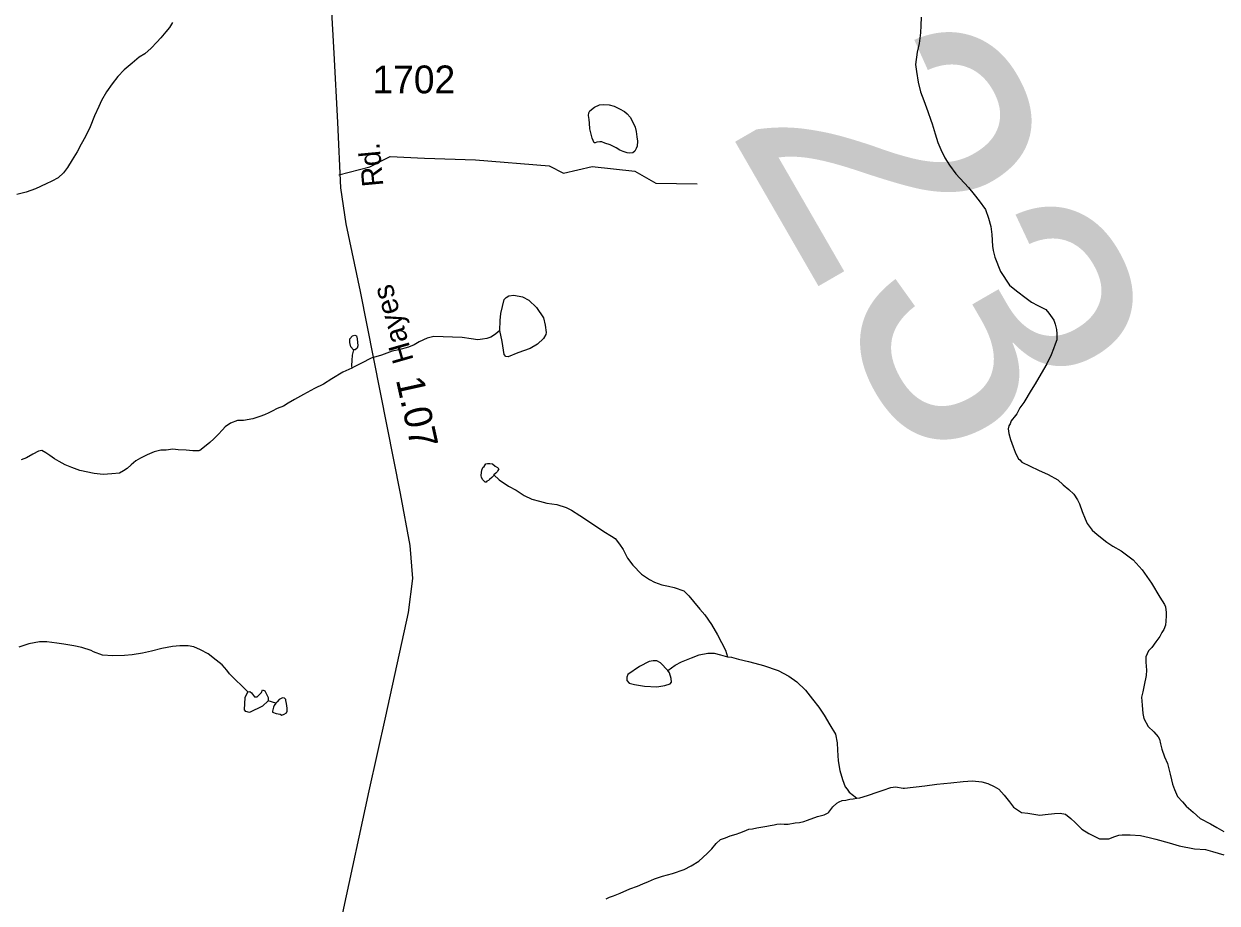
# Model space of a CAD drawing. Extents: x 2056842 to 2160602, y 826753 to 1016856.
# Drawn here: x 2104548 to 2109914, y 859964 to 863916 of the extents above; entities that cross this region are included whole.
import ezdxf

# ---------------------------------------------------------------- set-up
doc = ezdxf.new("R2010")
doc.units = 0
for name, color, linetype in [('Exist Hydrographic Creek Single Shore', 7, 'Continuous'), ('Exist Hydrographic Misc Water Feature', 7, 'Continuous'), ('Exist Road Non-System Type 51', 7, 'Continuous'), ('Exist Road Secondary Mileage Hundredths English Label', 7, 'Continuous'), ('Exist Road Secondary Structure Standard Bridge Number Label', 7, 'Continuous'), ('Exist Road Secondary Type 51 Attributed', 7, 'Continuous'), ('Exist Road Secondary Type 51 Label', 7, 'Continuous'), ('Exist Road Secondary Type 51 Number Label', 7, 'Continuous')]:
    doc.layers.add(name, color=color, linetype=linetype)

msp = doc.modelspace()

# ---------------------------------------------------------------- linework, layer by layer
at = {"layer": 'Exist Hydrographic Creek Single Shore'}
for points in [[(2108583.2, 863946), (2108581.5, 863908.1), (2108579.5, 863875.9), (2108573.7, 863828.1), (2108565.7, 863788), (2108558.2, 863733.9), (2108562.1, 863702.1), (2108570.3, 863654.2), (2108580.3, 863610.1), (2108594.9, 863572.1), (2108612.5, 863522.4), (2108626.6, 863482.5), (2108632.8, 863466.2), (2108646.7, 863422.2), (2108658.8, 863382.4), (2108670.9, 863350.5), (2108689.2, 863314.4), (2108711.1, 863280.7), (2108739.6, 863242.6), (2108795.8, 863181), (2108821.9, 863149), (2108844, 863120.9), (2108871.7, 863081), (2108886.2, 863043.1), (2108896.1, 863005.2), (2108900.2, 862969.2), (2108904.5, 862917.4), (2108906.5, 862897.2), (2108914.7, 862867.2), (2108940.6, 862803.6), (2108981, 862741.5), (2109011.1, 862715.8), (2109055, 862683.6), (2109078.8, 862665.8), (2109107.1, 862649.7), (2109129.2, 862639.9), (2109143.4, 862632.1), (2109157.1, 862616.2), (2109179.1, 862584.1), (2109185.4, 862566), (2109191.6, 862542.4), (2109193.4, 862522.3), (2109193.8, 862496.2), (2109185.8, 862476.3), (2109177.6, 862456), (2109168, 862427.9), (2109148.1, 862388), (2109122.1, 862344), (2109096.2, 862298), (2109078.4, 862269.8), (2109044.7, 862213.7), (2109026.7, 862189.7), (2109012.6, 862163.7), (2109007, 862155.7), (2108988.6, 862131.7), (2108982.8, 862117.6), (2108976.9, 862109.6), (2108974.8, 862095.7), (2108977.1, 862075.5), (2108985.3, 862047.8), (2108996.8, 862015.6), (2109005.2, 861991.6), (2109015, 861971.9), (2109021.4, 861961.6), (2109027.3, 861955.8), (2109035.3, 861945.7), (2109111.4, 861909.8), (2109153.6, 861890), (2109197.7, 861866.3), (2109221.7, 861844.5), (2109247.8, 861822.6), (2109269.9, 861802.6), (2109285.9, 861776.7), (2109295.7, 861758.5), (2109307.8, 861724.6), (2109320.1, 861690.8), (2109330, 861671), (2109352.1, 861640.8), (2109374.3, 861620.9), (2109418.4, 861587), (2109444.8, 861569.2), (2109482.3, 861547.2), (2109506.5, 861529.4), (2109536.5, 861507.5), (2109576.9, 861461.5), (2109619.1, 861401.6), (2109656.8, 861339.8), (2109677.1, 861306), (2109681.4, 861296), (2109685.1, 861269.8), (2109685.3, 861256), (2109683.5, 861232), (2109681.8, 861213.9), (2109673.8, 861194), (2109665.4, 861179.9), (2109655.8, 861162), (2109637.8, 861137.9), (2109619.7, 861113.8)], [(2106022.5, 862368.5), (2105982.3, 862350.2), (2105932.9, 862320.4), (2105894.7, 862296.1), (2105854.8, 862277.8), (2105804.9, 862249.6), (2105765.1, 862227.7), (2105737.1, 862211.6), (2105715.1, 862197.6), (2105687.6, 862187.5), (2105665.1, 862175.5), (2105649.3, 862167.3), (2105629.4, 862159.4), (2105609.3, 862151.1), (2105577.3, 862140.9), (2105535.3, 862133.1), (2105509.4, 862133), (2105477.3, 862120.8), (2105453.7, 862104.9), (2105441.6, 862090.8), (2105421.7, 862070.7), (2105401.8, 862050.6), (2105383.7, 862034.8), (2105359.6, 862014.5), (2105339.9, 861998.4), (2105334.1, 861996.4), (2105307.7, 861996.3), (2105277.7, 862000.1), (2105241.9, 862001.8), (2105218.1, 862003.8), (2105188.1, 861999.9), (2105163.7, 861999.9), (2105133.6, 861991.9), (2105101.8, 861979.7), (2105071.9, 861963.5), (2105052.2, 861951.5), (2105030, 861933.4), (2105012, 861917.4), (2104995.8, 861907.2), (2104978.6, 861897.3), (2104944.1, 861893.2), (2104904.3, 861891.1), (2104864.1, 861894.7), (2104800.2, 861908.9), (2104764.3, 861922.5), (2104733.9, 861934.4), (2104706.1, 861948.3), (2104686, 861960.3), (2104664, 861976.2), (2104646, 861988.2), (2104628.1, 861998.3), (2104614.2, 861995.9), (2104587.9, 861982.1), (2104559.8, 861966), (2104536.1, 861955.8)], [(2106661.8, 861888.6), (2106685.8, 861866.6), (2106728.1, 861838.7), (2106761.9, 861820.7), (2106798.4, 861796.9), (2106832.4, 861779.2), (2106866.3, 861771.2), (2106900.3, 861761.1), (2106944.4, 861755.3), (2106986.2, 861741.6), (2107010.2, 861729.8), (2107048.8, 861705.7), (2107100.4, 861671.9), (2107156.6, 861634.3), (2107190.7, 861614.1), (2107207.1, 861602.3), (2107226.8, 861578.2), (2107242.8, 861554.2), (2107262.8, 861514.2), (2107287, 861482.7), (2107325.4, 861442.8), (2107361.3, 861418.6), (2107383.6, 861406.7), (2107417.3, 861394.7), (2107447.2, 861388.9), (2107473, 861383), (2107515.5, 861367.2), (2107537.8, 861345.3), (2107559.4, 861319.2), (2107587.6, 861285.3), (2107609.8, 861259.7), (2107639.7, 861215.8), (2107667.8, 861169.7), (2107702.5, 861101.6), (2107712.3, 861071.6)], [(2105554.6, 860913.5), (2105472.9, 860995), (2105461.1, 861010.6), (2105439.1, 861034.6), (2105413.1, 861056.9), (2105376.4, 861084.7), (2105342.5, 861102.5), (2105312.4, 861116.3), (2105286.8, 861120.2), (2105248.6, 861120.3), (2105216.6, 861118.3), (2105168.6, 861108.1), (2105122.5, 861096), (2105080.7, 861087.7), (2105034.7, 861079.7), (2105000.9, 861077.5), (2104948.6, 861075.3), (2104900.9, 861079.3), (2104860.7, 861093.1), (2104850.6, 861099.1), (2104808.8, 861112.7), (2104772.7, 861120.6), (2104728.4, 861128.5), (2104696.4, 861132.5), (2104650.7, 861138.3), (2104618.3, 861138.3), (2104570.7, 861130.2), (2104524.6, 861114)], [(2109619.7, 861113.8), (2109606, 861097.7), (2109593.9, 861071.4), (2109594.1, 861047.4), (2109596.3, 861011.9), (2109594.5, 860987.8), (2109586.3, 860943.6), (2109580.3, 860913.6), (2109574.6, 860889.7), (2109576.9, 860853.8), (2109580.5, 860815.8), (2109585.1, 860793.7), (2109604.5, 860757.8), (2109628.9, 860733.8), (2109649.2, 860711.7), (2109655.2, 860701.8), (2109659.3, 860680.2), (2109665.4, 860656.1), (2109677.1, 860622.3), (2109691.3, 860592.1), (2109703.6, 860543.9), (2109709.5, 860518.3), (2109713.8, 860498.2), (2109721.8, 860474.3), (2109736, 860444.2), (2109758.3, 860420.1), (2109774.1, 860400.2), (2109806.1, 860372.7), (2109838.3, 860344.6), (2109884, 860320.6), (2109912.3, 860304.6), (2109944.3, 860286.8)], [(2107712.3, 861071.6), (2107730.2, 861069.8), (2107762.1, 861060), (2107806, 861050.2), (2107834.5, 861042.2), (2107874.5, 861032.5), (2107940.5, 861010.3), (2107988.5, 860984.8), (2108024.6, 860959.1), (2108063, 860921.2), (2108094.9, 860881), (2108122.8, 860845.1), (2108147, 860809.4), (2108172.9, 860765.3), (2108197.5, 860723.4), (2108205.1, 860685.4), (2108207.5, 860651.4), (2108209.8, 860603.5), (2108217.8, 860559.7), (2108229.7, 860519.3), (2108241.8, 860487.5), (2108250, 860475.7), (2108260, 860463.6), (2108278.1, 860447.5), (2108294.1, 860435.8)], [(2108294.1, 860435.8), (2108307.8, 860437.7), (2108341.8, 860448), (2108390, 860464.3), (2108412.2, 860472.3), (2108446, 860484.2), (2108468.1, 860486.5), (2108502, 860480.6), (2108507.9, 860480.5), (2108599.8, 860490.9), (2108653.7, 860498.9), (2108716, 860505), (2108771.8, 860511.1), (2108813.9, 860513.3), (2108856.1, 860509.3), (2108883.6, 860501.5), (2108912.1, 860487.8), (2108931.8, 860475.9), (2108955.8, 860449.9), (2108980.2, 860419.9), (2108997.8, 860396.1), (2109034.3, 860371.9), (2109062.4, 860368), (2109090.3, 860364.2), (2109116.3, 860360.3), (2109140.1, 860362.3), (2109182.5, 860366.5), (2109208.4, 860368.7), (2109232.4, 860364.6), (2109256.2, 860344.8), (2109276, 860326.8), (2109306.4, 860297), (2109336.7, 860276.9), (2109384.5, 860253.1), (2109416.5, 860253.2), (2109426.6, 860253.3), (2109454.6, 860263.6), (2109472.7, 860269.4), (2109486.6, 860271.3), (2109522.3, 860271.6), (2109568.9, 860267.8), (2109608.6, 860259.7), (2109638.4, 860251.9), (2109698.7, 860235.9), (2109742.7, 860222.4), (2109812.3, 860208.6), (2109862.5, 860204.7), (2109892.6, 860196.8), (2109944.5, 860180.9)], [(2107165.9, 859984.2), (2107181.6, 859990.4), (2107199.7, 859996.6), (2107229.8, 860008.6), (2107273.5, 860028.8), (2107307.8, 860040.7), (2107331.5, 860050.9), (2107357.4, 860061.1), (2107383.2, 860073), (2107419.3, 860085), (2107465, 860097.1), (2107517.3, 860115.2), (2107549.3, 860131.5), (2107583.1, 860153.5), (2107621.3, 860188), (2107641.2, 860207.6), (2107660.9, 860231.8), (2107680.7, 860249.9), (2107703.1, 860257.9), (2107724.8, 860266), (2107750.7, 860274.2), (2107767.1, 860280.2), (2107786.8, 860288.2), (2107808.5, 860296.3), (2107824.5, 860298.4), (2107844.6, 860302.2), (2107870.4, 860306.4), (2107888.5, 860310.6), (2107904.7, 860312.5), (2107922.7, 860316.7), (2107934.4, 860318.6), (2107950.6, 860320.6), (2107966.4, 860318.7), (2107984.6, 860318.7), (2108016.6, 860324.8), (2108036.7, 860327.1), (2108054.8, 860331.2), (2108072.6, 860337), (2108116.3, 860353.1), (2108146.4, 860361.1), (2108164.3, 860369.4), (2108168.4, 860373.2), (2108186.4, 860397.3), (2108204.4, 860413.6), (2108214.3, 860419.5), (2108228, 860425.5), (2108244.2, 860427.5), (2108262.3, 860431.7), (2108277.9, 860433.7), (2108294.1, 860435.8)]]:
    msp.add_lwpolyline(points, dxfattribs=at)
at = {"layer": 'Exist Hydrographic Misc Water Feature'}
for points in [[(2105216.2, 863921.7), (2105202.3, 863899.5), (2105186.3, 863879.6), (2105164.1, 863853.8), (2105146.3, 863833.4), (2105120.3, 863807.2), (2105092.6, 863781.4), (2105066.5, 863765.5), (2105034.5, 863739), (2104998.5, 863709.2), (2104971, 863679), (2104944.7, 863646.8), (2104919.3, 863610.9), (2104897.2, 863570.8), (2104885.3, 863544.7), (2104865.4, 863502.6), (2104845.7, 863452.4), (2104825.4, 863410.4), (2104805.9, 863374.5), (2104787.9, 863340.2), (2104765.7, 863304.2), (2104744.4, 863270.2), (2104726.4, 863246.1), (2104702.2, 863224.2), (2104674.1, 863208.2), (2104648.2, 863196.3), (2104600.4, 863173.9), (2104558.6, 863160), (2104516.4, 863149.7)], [(2107113.2, 863381.5), (2107103.3, 863401.7), (2107092.9, 863443.5), (2107091, 863469.7), (2107089.4, 863485.4), (2107086.7, 863503.6), (2107088.8, 863515.5), (2107093.1, 863525.4), (2107114.8, 863541.6), (2107136.9, 863551.6), (2107156.8, 863553.9), (2107180.6, 863551.8), (2107202.6, 863545.7), (2107226.6, 863534), (2107248.9, 863522.1), (2107260.8, 863512.2), (2107274.7, 863496.3), (2107287, 863474.1), (2107297.1, 863452.3), (2107301, 863432.2), (2107305.1, 863408.5), (2107307.3, 863388.2), (2107305.3, 863366.3), (2107301.6, 863356.2), (2107295.2, 863344.2), (2107287, 863336.1), (2107273.1, 863334.2), (2107261.6, 863335.9), (2107243.4, 863342), (2107227.4, 863348), (2107211.4, 863358.2), (2107185.1, 863371.9), (2107161.3, 863379.9), (2107147.4, 863385.6), (2107137.4, 863385.6), (2107125.1, 863383.8), (2107117.1, 863381.7), (2107113.2, 863381.5)], [(2106689, 862538.5), (2106689.4, 862583.2), (2106692.5, 862614.9), (2106708.3, 862676.4), (2106716.6, 862686.5), (2106729.2, 862693.5), (2106752, 862696), (2106790.6, 862688.4), (2106819.1, 862673.8), (2106854, 862640.9), (2106884.3, 862595.3), (2106891.9, 862562.3), (2106896.4, 862529.4), (2106895.1, 862520.5), (2106884.3, 862502.2), (2106857.8, 862476.8), (2106825.5, 862457.2), (2106769.8, 862436.9), (2106726.1, 862419.2), (2106715.3, 862421.1), (2106707.7, 862429.9), (2106698.8, 862488.2), (2106689, 862538.5)], [(2106030.2, 862450.4), (2106017.6, 862464.9), (2106013.2, 862483.3), (2106014.5, 862499.8), (2106026.5, 862513.1), (2106036.6, 862516.2), (2106043.6, 862513.1), (2106047.4, 862500.4), (2106049.3, 862469.3), (2106047.4, 862458.6), (2106037.9, 862450.3), (2106030.2, 862450.4)], [(2106689, 862538.5), (2106680.1, 862530.6), (2106670, 862522.3), (2106656.1, 862512.2), (2106648.3, 862508.2), (2106630.3, 862502.4), (2106610, 862498.2), (2106590.1, 862496.3), (2106560.1, 862500), (2106518.3, 862506), (2106476.1, 862507.9), (2106433.8, 862509.9), (2106392, 862511.3), (2106361.8, 862503.7), (2106326, 862487.2), (2106302.4, 862473.4), (2106278.2, 862463.2), (2106234.1, 862451.2), (2106204.2, 862444.8), (2106156.2, 862426.9), (2106110, 862412.8), (2106066.4, 862390.6), (2106032.7, 862374.2), (2106022.5, 862368.5)], [(2106030.2, 862450.4), (2106028.2, 862444.2), (2106024.3, 862426.2), (2106022.5, 862402.5), (2106020.6, 862380.5), (2106022.5, 862368.5)], [(2106661.8, 861888.6), (2106660, 861884.3), (2106651.8, 861876.7), (2106641.9, 861868.5), (2106637.8, 861864.2), (2106630.1, 861860.5), (2106626.4, 861856.2), (2106622.1, 861856.5), (2106612, 861866.5), (2106605.9, 861876.4), (2106604.2, 861886.3), (2106606.1, 861900.2), (2106607.7, 861910.2), (2106611.8, 861922.5), (2106617.8, 861926.5), (2106621.9, 861934.4), (2106625.5, 861938.3), (2106633.5, 861940.3), (2106643.8, 861940.4), (2106655.7, 861938.6), (2106667.8, 861928.6), (2106677.8, 861922.7), (2106684, 861916.4), (2106679.7, 861908.5), (2106677.6, 861904.4), (2106670, 861896.7), (2106661.8, 861888.6)], [(2107443.8, 861010.1), (2107476.5, 861033.2), (2107504.6, 861049.2), (2107550.5, 861067.3), (2107584.4, 861079.7), (2107624.4, 861087.4), (2107652, 861087.7), (2107680.5, 861079.7), (2107712.3, 861071.6)], [(2107443.8, 861010.1), (2107411.5, 861044.3), (2107395, 861052.6), (2107378.6, 861053.8), (2107360.2, 861050), (2107316.5, 861027.9), (2107263.4, 860991.8), (2107258.9, 860979.1), (2107259.6, 860965.2), (2107269.7, 860952.5), (2107293.8, 860946.8), (2107339.3, 860939.2), (2107393.8, 860936.7), (2107430.5, 860941.7), (2107453.9, 860950), (2107460.9, 860957.6), (2107459.6, 860973.4), (2107450.8, 860999.4), (2107443.8, 861010.1)], [(2105647, 860873), (2105620.4, 860848.9), (2105562.1, 860821), (2105545.7, 860824.8), (2105540.6, 860833.7), (2105543.2, 860888.2), (2105554.6, 860913.5)], [(2105554.6, 860913.5), (2105563.4, 860916), (2105571, 860909.7), (2105584.9, 860890.7), (2105597.6, 860892), (2105616.6, 860911), (2105620.4, 860922.4), (2105631.8, 860918.6), (2105647, 860888.2), (2105647, 860873)], [(2105680.4, 860862.7), (2105647, 860873)], [(2105686.5, 860869.1), (2105680.4, 860862.7), (2105674, 860852.7), (2105670.1, 860844.8), (2105668.1, 860832.9), (2105666.2, 860826.6), (2105666, 860822.6), (2105682, 860817), (2105700.1, 860813), (2105708.5, 860808.9), (2105718.3, 860813.1), (2105728.4, 860818.8), (2105732.3, 860826.8), (2105732.3, 860832.9), (2105732.5, 860841), (2105728.6, 860861.1), (2105726.1, 860874.8), (2105726.3, 860878.8), (2105720.2, 860885.1), (2105710.3, 860886.9), (2105702.3, 860882.8), (2105696.2, 860878.9), (2105686.5, 860869.1)]]:
    msp.add_lwpolyline(points, dxfattribs=at)
at = {"layer": 'Exist Road Non-System Type 51'}
msp.add_lwpolyline([(2105963.9, 863236.8), (2106103.9, 863273.4), (2106195.3, 863319.1), (2106349, 863312.9), (2106579.5, 863304.6), (2106909.8, 863277.6), (2106975.2, 863245.3), (2107104, 863274.4), (2107295.1, 863253.7), (2107390.6, 863199.6), (2107575.5, 863197.5)], dxfattribs=at)
at = {"layer": 'Exist Road Secondary Type 51 Attributed'}
msp.add_lwpolyline([(2105876.5, 864701), (2105881.4, 864661), (2105898.6, 864556.6), (2105941.2, 863784.5), (2105957.8, 863472.7), (2105972.3, 863179.7), (2105996.2, 863016.5), (2106060.6, 862713.1), (2106240.2, 861805.9), (2106283.8, 861571), (2106296.3, 861423.5), (2106275.5, 861269.7), (2106174.8, 860805.2), (2106100, 860468.5), (2105980.6, 859920.8), (2105945.3, 859746.2), (2105901.7, 859505.2), (2105874.7, 859326.4), (2105849.8, 859105.6)], dxfattribs=at)

# ---------------------------------------------------------------- texts
at = {"layer": 'Exist Road Secondary Mileage Hundredths English Label'}
msp.add_text('1.07', height=125, rotation=282.5272, dxfattribs=at).set_placement((2106220.4, 862316.8))
at = {"layer": 'Exist Road Secondary Structure Standard Bridge Number Label'}
msp.add_text('23', height=1230.31, rotation=300, dxfattribs=at).set_placement((2107705.2, 863457.9))
at = {"layer": 'Exist Road Secondary Type 51 Label'}
for s, rotation, p in [('Rd.', 95.3528, (2106165, 863188.2)), ('Hayes', 105.9498, (2106301.7, 862405.6))]:
    msp.add_text(s, height=95, rotation=rotation, dxfattribs=at).set_placement(p)
at = {"layer": 'Exist Road Secondary Type 51 Number Label'}
msp.add_text('1702', height=125, dxfattribs=at).set_placement((2106115.8, 863603.7))

doc.saveas('drawing.dxf')
